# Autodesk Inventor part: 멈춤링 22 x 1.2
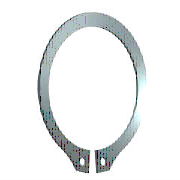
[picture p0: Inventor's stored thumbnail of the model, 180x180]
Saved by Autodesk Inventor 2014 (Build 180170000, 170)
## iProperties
IsCustomPart: 0
Created: 2009-02
Part Number: 멈춤링 22 x 1.2
Material: Steel, Mild
Description: 리테이닝 링(C형)
Document SubType Name: Modeling
Standard: KS B 1336
Designer: SeoGD™
Standards Organization: KS
Language: ko-KR
Size Designation: 22 x 1.2
Categories: <MemberInstance><Categories><Category DisplayName="샤프트 부품" InternalName="7f7aeb1f-a693-4053-b835-cee3144e0d98" Mnemonic="SHFT"><Category DisplayName="써클립" Inter
Density: 7.86 g/cm^3
Appearance: Metal-Steel
Mass: 1.8286 g
Surface Area: 5.91219 cm^2
Volume: 0.232646 cm^3
Author: SeoGD™
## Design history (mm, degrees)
sketch "스케치1"
  geometry: L1 (-6, 0)-(6, 0) reference; L2 (0, 20.189)-(0, -80.536) reference; L3 (-48.09, 0)-(48.09, 0) reference; L4 (-0.5, -21.488)-(-0.5, -25.588); L5 (-0.5, -6.54)-(-0.5, -13.29); L6 (-2.795, 2.7)-(3.672, 2.7); L7 (0.5, -6.54)-(0.5, -13.29); L8 (0.5, -21.488)-(0.5, -25.588); C1 r 1 at (-2, -23.437); C2 r 1 at (2, -23.437); A1 r 10.5 centre (0, -11) between (0.5, -21.488) and (-0.5, -21.488); A2 r 13.025 centre (0, -10.325) between (5.149, -22.289) and (-5.149, -22.289); A3 r 14.597 centre (0, -11) between (-2.318, -25.411) and (-0.5, -25.588); A4 r 2 centre (-2, -23.437) between (-3.97, -23.781) and (-2.318, -25.411); A5 r 2 centre (-5.94, -24.126) between (-3.97, -23.781) and (-5.149, -22.289); A6 r 2 centre (5.94, -24.126) between (5.149, -22.289) and (3.97, -23.781); A7 r 2 centre (2, -23.437) between (2.318, -25.411) and (3.97, -23.781); A8 r 14.597 centre (0, -11) between (0.5, -25.588) and (2.318, -25.411)
  constraints: 16 point on circle, 12 end point, 10 centre point, 9 symmetric about line, 5 point on line, 4 tangent, 3 coincident, 2 horizontal, 1 perpendicular, 1 vertical, 5 other
  dimensions: "d0" = 21 diameter of A1 (= ND); "d1" = 4.1 distance of L4.end L4.start (= SRB2); "d6" = 0.5 distance between parallel lines of L2 L5 (= 0.25 x SD5); "d7" = 2.7 distance between parallel lines of L6 L3 (= SRB1); "d8" = 0.675 distance of A1.centre A2.centre (= 0.25 x SRB1); "d9" = 2 radius of A4 (= SD5); "d10" = 2 radius of A5 (= SD5); "d11" = 1.5 distance from line of L4 A4.centre (= 0.75 x SD5); "d12" = 2 diameter of C1 (= SD5); "d13" = 2 diameter of C2 (= SD5); "d14" = 11 distance from line of A1.centre L1 (= 0.5 x WD)
extrude "본체" new body sketch "스케치1" distance "d2" = 1.2 (= SD); taper "d3" = 0 deg
workaxis "Work Axis1"
workplane "Work Plane1"
body "Solid1"
other parameters: "WD" = 22 (= WDMIN) [user parameter; used in 1 equation term], "SD" = 1.2 [user parameter; used in 1 equation term], "SRB1" = 2.7 [user parameter; used in 2 equation terms], "ND" = 21 [user parameter; used in 1 equation term], "SRB2" = 4.1 [user parameter; used in 1 equation term], "SD5" = 2 [user parameter; used in 6 equation terms], "d15" = 0, "d16" = 0, "d17" = 0, "d41" = 0, "d42" = 0, "WDMIN" = 22 [user parameter; used in 1 equation term], "SD3" = 20.5 [user parameter], "WDMAX" = 24 [user parameter]
